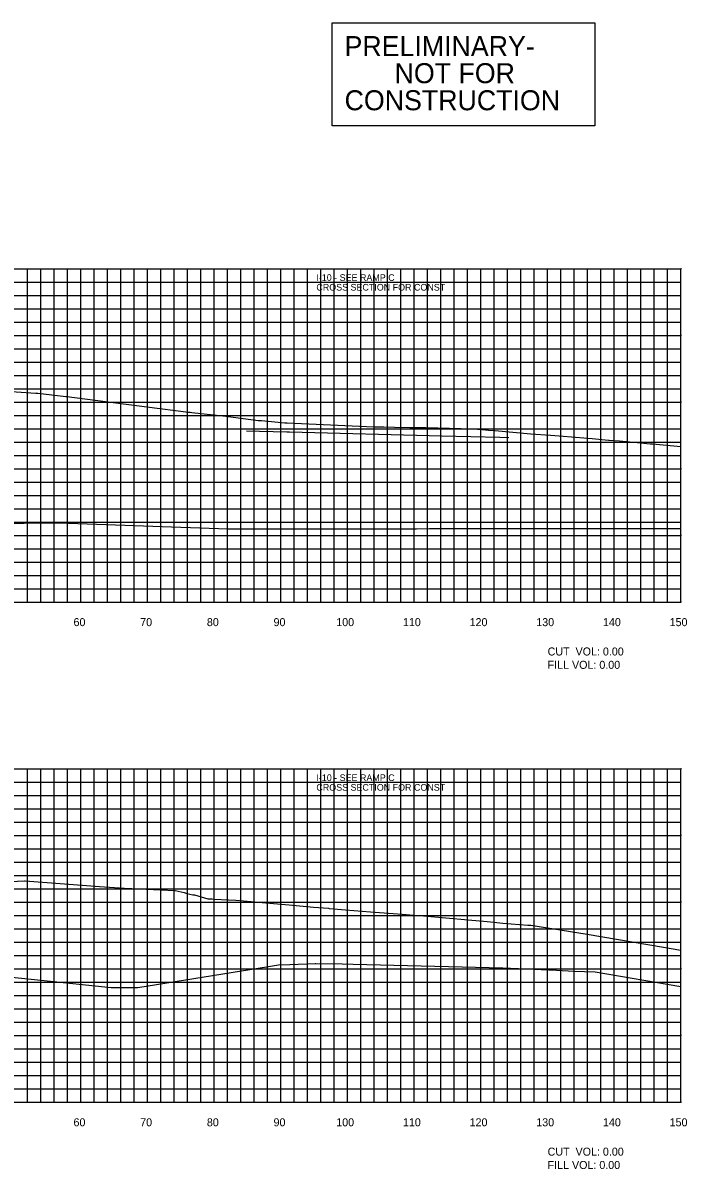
# Model space of a CAD drawing. Extents: x 1800880 to 1814006, y 250083 to 250560.
# Drawn here: x 1809822.3 to 1809921.9, y 250089.4 to 250261.3 of the extents above; entities that cross this region are included whole.
import ezdxf

# ---------------------------------------------------------------- set-up
doc = ezdxf.new("R2010")
doc.units = 0
for name, color, linetype in [('CL-CNST', 7, 'Continuous'), ('DESIGN - DRAINAGE - Bridges', 7, 'Continuous'), ('DRAINAGETXT', 7, 'Continuous'), ('EPTEXT', 7, 'Continuous'), ('Level 32', 7, 'Continuous'), ('Level 46', 7, 'Continuous'), ('Level 62', 7, 'Continuous')]:
    doc.layers.add(name, color=color, linetype=linetype)

msp = doc.modelspace()

# ---------------------------------------------------------------- linework, layer by layer
at = {"layer": 'CL-CNST'}
for points in [[(1809818.3, 250206.17), (1809824.23, 250205.75), (1809824.54, 250205.75), (1809828.73, 250205.28), (1809828.91, 250205.28), (1809840.91, 250203.73), (1809847.13, 250202.9), (1809847.4, 250202.9), (1809847.65, 250202.89), (1809852.73, 250202.3), (1809857.58, 250201.65), (1809857.93, 250201.65), (1809858.08, 250201.65), (1809861.59, 250201.34), (1809861.95, 250201.3), (1809874.92, 250200.73), (1809876.2, 250200.71), (1809876.42, 250200.71), (1809878.06, 250200.68), (1809880.35, 250200.64), (1809882.75, 250200.6), (1809884.52, 250200.56), (1809889.81, 250200.43), (1809891.17, 250200.31), (1809892.11, 250200.23), (1809893.07, 250200.15), (1809898.46, 250199.69), (1809901.44, 250199.46), (1809902.75, 250199.35), (1809905.18, 250199.17), (1809907.67, 250198.95), (1809910.14, 250198.74), (1809910.22, 250198.74), (1809911.77, 250198.61), (1809913.32, 250198.47), (1809914.41, 250198.38), (1809916.4, 250198.19), (1809916.75, 250198.16), (1809921, 250197.76)], [(1809819.38, 250132.51), (1809822.53, 250132.62), (1809822.64, 250132.62), (1809833.8, 250131.77), (1809838.31, 250131.48), (1809838.66, 250131.49), (1809845.09, 250131.21), (1809845.16, 250131.21), (1809846.48, 250130.87), (1809846.91, 250130.76), (1809847.8, 250130.53), (1809848.05, 250130.52), (1809850.04, 250129.95), (1809850.69, 250129.92), (1809850.97, 250129.91), (1809853.14, 250129.79), (1809854.23, 250129.73), (1809856.54, 250129.53), (1809858.75, 250129.34), (1809862.26, 250129.03), (1809865.91, 250128.71), (1809868.12, 250128.52), (1809868.23, 250128.51), (1809868.29, 250128.5), (1809870.71, 250128.31), (1809874.46, 250128.01), (1809877.86, 250127.73), (1809879.19, 250127.64), (1809881.53, 250127.46), (1809881.97, 250127.43), (1809882.39, 250127.4), (1809889.07, 250126.79), (1809891.93, 250126.52), (1809893.38, 250126.39), (1809894.26, 250126.31), (1809898.02, 250126), (1809898.38, 250126), (1809898.49, 250126), (1809906.64, 250124.67), (1809906.91, 250124.66), (1809918.38, 250122.67), (1809921, 250122.25)]]:
    msp.add_lwpolyline(points, dxfattribs=at)
at = {"layer": 'DESIGN - DRAINAGE - Bridges'}
for p, q in [((1809921, 250174.43), (1809921, 250224.43)), ((1809921.06, 250224.43), (1809921, 250224.43)), ((1809921.06, 250214.43), (1809921, 250214.43)), ((1809921.06, 250204.43), (1809921, 250204.43)), ((1809921.06, 250194.43), (1809921, 250194.43)), ((1809921.06, 250184.43), (1809921, 250184.43)), ((1809621, 250174.43), (1809921, 250174.43)), ((1809831, 250174.37), (1809831, 250174.43)), ((1809841, 250174.37), (1809841, 250174.43)), ((1809851, 250174.37), (1809851, 250174.43)), ((1809861, 250174.37), (1809861, 250174.43)), ((1809871, 250174.37), (1809871, 250174.43)), ((1809881, 250174.37), (1809881, 250174.43)), ((1809891, 250174.37), (1809891, 250174.43)), ((1809901, 250174.37), (1809901, 250174.43)), ((1809911, 250174.37), (1809911, 250174.43)), ((1809921, 250174.37), (1809921, 250174.43)), ((1809921.06, 250174.43), (1809921, 250174.43)), ((1809921, 250099.43), (1809921, 250149.43)), ((1809921.06, 250149.43), (1809921, 250149.43)), ((1809921.06, 250139.43), (1809921, 250139.43)), ((1809921.06, 250129.43), (1809921, 250129.43)), ((1809921.06, 250119.43), (1809921, 250119.43)), ((1809921.06, 250109.43), (1809921, 250109.43)), ((1809621, 250099.43), (1809921, 250099.43)), ((1809831, 250099.37), (1809831, 250099.43)), ((1809841, 250099.37), (1809841, 250099.43)), ((1809851, 250099.37), (1809851, 250099.43)), ((1809861, 250099.37), (1809861, 250099.43)), ((1809871, 250099.37), (1809871, 250099.43)), ((1809881, 250099.37), (1809881, 250099.43)), ((1809891, 250099.37), (1809891, 250099.43)), ((1809901, 250099.37), (1809901, 250099.43)), ((1809911, 250099.37), (1809911, 250099.43)), ((1809921, 250099.37), (1809921, 250099.43)), ((1809921.06, 250099.43), (1809921, 250099.43))]:
    msp.add_line(p, q, dxfattribs=at)
at = {"layer": 'Level 32'}
msp.add_lwpolyline([(1809868.68, 250261.29), (1809908.08, 250261.29), (1809908.08, 250245.85), (1809868.68, 250245.85)], close=True, dxfattribs=at)
at = {"layer": 'Level 46'}
for p, q in [((1809621, 250224.43), (1809921, 250224.43)), ((1809823, 250174.43), (1809823, 250224.43)), ((1809825, 250174.43), (1809825, 250224.43)), ((1809827, 250174.43), (1809827, 250224.43)), ((1809829, 250174.43), (1809829, 250224.43)), ((1809831, 250174.43), (1809831, 250224.43)), ((1809833, 250174.43), (1809833, 250224.43)), ((1809835, 250174.43), (1809835, 250224.43)), ((1809837, 250174.43), (1809837, 250224.43)), ((1809839, 250174.43), (1809839, 250224.43)), ((1809841, 250174.43), (1809841, 250224.43)), ((1809843, 250174.43), (1809843, 250224.43)), ((1809845, 250174.43), (1809845, 250224.43)), ((1809847, 250174.43), (1809847, 250224.43)), ((1809849, 250174.43), (1809849, 250224.43)), ((1809851, 250174.43), (1809851, 250224.43)), ((1809853, 250174.43), (1809853, 250224.43)), ((1809855, 250174.43), (1809855, 250224.43)), ((1809857, 250174.43), (1809857, 250224.43)), ((1809859, 250174.43), (1809859, 250224.43)), ((1809861, 250174.43), (1809861, 250224.43)), ((1809863, 250174.43), (1809863, 250224.43)), ((1809865, 250174.43), (1809865, 250224.43)), ((1809867, 250174.43), (1809867, 250224.43)), ((1809869, 250174.43), (1809869, 250224.43)), ((1809871, 250174.43), (1809871, 250224.43)), ((1809873, 250174.43), (1809873, 250224.43)), ((1809875, 250174.43), (1809875, 250224.43)), ((1809877, 250174.43), (1809877, 250224.43)), ((1809879, 250174.43), (1809879, 250224.43)), ((1809881, 250174.43), (1809881, 250224.43)), ((1809883, 250174.43), (1809883, 250224.43)), ((1809885, 250174.43), (1809885, 250224.43)), ((1809887, 250174.43), (1809887, 250224.43)), ((1809889, 250174.43), (1809889, 250224.43)), ((1809891, 250174.43), (1809891, 250224.43)), ((1809893, 250174.43), (1809893, 250224.43)), ((1809895, 250174.43), (1809895, 250224.43)), ((1809897, 250174.43), (1809897, 250224.43)), ((1809899, 250174.43), (1809899, 250224.43)), ((1809901, 250174.43), (1809901, 250224.43)), ((1809903, 250174.43), (1809903, 250224.43)), ((1809905, 250174.43), (1809905, 250224.43)), ((1809907, 250174.43), (1809907, 250224.43)), ((1809909, 250174.43), (1809909, 250224.43)), ((1809911, 250174.43), (1809911, 250224.43)), ((1809913, 250174.43), (1809913, 250224.43)), ((1809915, 250174.43), (1809915, 250224.43)), ((1809917, 250174.43), (1809917, 250224.43)), ((1809919, 250174.43), (1809919, 250224.43)), ((1809921, 250174.43), (1809921, 250224.43)), ((1809621, 250222.43), (1809921, 250222.43)), ((1809621, 250220.43), (1809921, 250220.43)), ((1809621, 250218.43), (1809921, 250218.43)), ((1809621, 250216.43), (1809921, 250216.43)), ((1809621, 250214.43), (1809921, 250214.43)), ((1809621, 250212.43), (1809921, 250212.43)), ((1809621, 250210.43), (1809921, 250210.43)), ((1809621, 250208.43), (1809921, 250208.43)), ((1809621, 250206.43), (1809921, 250206.43)), ((1809621, 250204.43), (1809921, 250204.43)), ((1809621, 250202.43), (1809921, 250202.43)), ((1809621, 250200.43), (1809921, 250200.43)), ((1809621, 250198.43), (1809921, 250198.43)), ((1809621, 250196.43), (1809921, 250196.43)), ((1809621, 250194.43), (1809921, 250194.43)), ((1809621, 250192.43), (1809921, 250192.43)), ((1809621, 250190.43), (1809921, 250190.43)), ((1809621, 250188.43), (1809921, 250188.43)), ((1809621, 250186.43), (1809921, 250186.43)), ((1809621, 250184.43), (1809921, 250184.43)), ((1809621, 250182.43), (1809921, 250182.43)), ((1809621, 250180.43), (1809921, 250180.43)), ((1809621, 250178.43), (1809921, 250178.43)), ((1809621, 250176.43), (1809921, 250176.43)), ((1809621, 250174.43), (1809921, 250174.43)), ((1809621, 250149.43), (1809921, 250149.43)), ((1809823, 250099.43), (1809823, 250149.43)), ((1809825, 250099.43), (1809825, 250149.43)), ((1809827, 250099.43), (1809827, 250149.43)), ((1809829, 250099.43), (1809829, 250149.43)), ((1809831, 250099.43), (1809831, 250149.43)), ((1809833, 250099.43), (1809833, 250149.43)), ((1809835, 250099.43), (1809835, 250149.43)), ((1809837, 250099.43), (1809837, 250149.43)), ((1809839, 250099.43), (1809839, 250149.43)), ((1809841, 250099.43), (1809841, 250149.43)), ((1809843, 250099.43), (1809843, 250149.43)), ((1809845, 250099.43), (1809845, 250149.43)), ((1809847, 250099.43), (1809847, 250149.43)), ((1809849, 250099.43), (1809849, 250149.43)), ((1809851, 250099.43), (1809851, 250149.43)), ((1809853, 250099.43), (1809853, 250149.43)), ((1809855, 250099.43), (1809855, 250149.43)), ((1809857, 250099.43), (1809857, 250149.43)), ((1809859, 250099.43), (1809859, 250149.43)), ((1809861, 250099.43), (1809861, 250149.43)), ((1809863, 250099.43), (1809863, 250149.43)), ((1809865, 250099.43), (1809865, 250149.43)), ((1809867, 250099.43), (1809867, 250149.43)), ((1809869, 250099.43), (1809869, 250149.43)), ((1809871, 250099.43), (1809871, 250149.43)), ((1809873, 250099.43), (1809873, 250149.43)), ((1809875, 250099.43), (1809875, 250149.43)), ((1809877, 250099.43), (1809877, 250149.43)), ((1809879, 250099.43), (1809879, 250149.43)), ((1809881, 250099.43), (1809881, 250149.43)), ((1809883, 250099.43), (1809883, 250149.43)), ((1809885, 250099.43), (1809885, 250149.43)), ((1809887, 250099.43), (1809887, 250149.43)), ((1809889, 250099.43), (1809889, 250149.43)), ((1809891, 250099.43), (1809891, 250149.43)), ((1809893, 250099.43), (1809893, 250149.43)), ((1809895, 250099.43), (1809895, 250149.43)), ((1809897, 250099.43), (1809897, 250149.43)), ((1809899, 250099.43), (1809899, 250149.43)), ((1809901, 250099.43), (1809901, 250149.43)), ((1809903, 250099.43), (1809903, 250149.43)), ((1809905, 250099.43), (1809905, 250149.43)), ((1809907, 250099.43), (1809907, 250149.43)), ((1809909, 250099.43), (1809909, 250149.43)), ((1809911, 250099.43), (1809911, 250149.43)), ((1809913, 250099.43), (1809913, 250149.43)), ((1809915, 250099.43), (1809915, 250149.43)), ((1809917, 250099.43), (1809917, 250149.43)), ((1809919, 250099.43), (1809919, 250149.43)), ((1809921, 250099.43), (1809921, 250149.43)), ((1809621, 250147.43), (1809921, 250147.43)), ((1809621, 250145.43), (1809921, 250145.43)), ((1809621, 250143.43), (1809921, 250143.43)), ((1809621, 250141.43), (1809921, 250141.43)), ((1809621, 250139.43), (1809921, 250139.43)), ((1809621, 250137.43), (1809921, 250137.43)), ((1809621, 250135.43), (1809921, 250135.43)), ((1809621, 250133.43), (1809921, 250133.43)), ((1809621, 250131.43), (1809921, 250131.43)), ((1809621, 250129.43), (1809921, 250129.43)), ((1809621, 250127.43), (1809921, 250127.43)), ((1809621, 250125.43), (1809921, 250125.43)), ((1809621, 250123.43), (1809921, 250123.43)), ((1809621, 250121.43), (1809921, 250121.43)), ((1809621, 250119.43), (1809921, 250119.43)), ((1809621, 250117.43), (1809921, 250117.43)), ((1809621, 250115.43), (1809921, 250115.43)), ((1809621, 250113.43), (1809921, 250113.43)), ((1809621, 250111.43), (1809921, 250111.43)), ((1809621, 250109.43), (1809921, 250109.43)), ((1809621, 250107.43), (1809921, 250107.43)), ((1809621, 250105.43), (1809921, 250105.43)), ((1809621, 250103.43), (1809921, 250103.43)), ((1809621, 250101.43), (1809921, 250101.43)), ((1809621, 250099.43), (1809921, 250099.43))]:
    msp.add_line(p, q, dxfattribs=at)
at = {"layer": 'Level 62'}
for points in [[(1809855.86, 250200.14), (1809857.77, 250200.09), (1809861.87, 250199.98), (1809862.28, 250199.97), (1809885.12, 250199.37), (1809893.81, 250199.15), (1809895.16, 250199.11)], [(1809621, 250186.58), (1809633.48, 250186.5), (1809635.86, 250186.5), (1809661.24, 250186.43), (1809666.01, 250186.45), (1809688.99, 250186.47), (1809695.84, 250186.51), (1809716.75, 250186.15), (1809725.4, 250186.2), (1809744.5, 250186.4), (1809762.12, 250186.29), (1809772.26, 250186.35), (1809789.71, 250186.64), (1809800.01, 250186.71), (1809817.25, 250186.24), (1809827.77, 250186.3), (1809853.03, 250185.43), (1809855.53, 250185.44), (1809881.36, 250185.44), (1809883.28, 250185.45), (1809909.23, 250185.45), (1809911.04, 250185.46), (1809921, 250185.46)], [(1809755.37, 250124.99), (1809757.56, 250124.76), (1809763.06, 250124.19), (1809781.58, 250122.26), (1809825, 250117.75), (1809835.53, 250116.65), (1809837.19, 250116.64), (1809839.55, 250116.63), (1809859.12, 250119.79), (1809860.64, 250120.04), (1809862.34, 250120.1), (1809866.16, 250120.23), (1809866.24, 250120.24), (1809870.18, 250120.21), (1809871.82, 250120.16), (1809894.28, 250119.58), (1809896.63, 250119.48), (1809902.31, 250119.23), (1809904.94, 250119.11), (1809908.14, 250118.97), (1809921, 250116.79)]]:
    msp.add_lwpolyline(points, dxfattribs=at)

# ---------------------------------------------------------------- texts
for s, p in [('60', (1809829.9, 250170.83)), ('70', (1809839.9, 250170.83)), ('80', (1809849.9, 250170.83)), ('90', (1809859.9, 250170.83)), ('100', (1809869.3, 250170.83)), ('110', (1809879.3, 250170.83)), ('120', (1809889.3, 250170.83)), ('130', (1809899.3, 250170.83)), ('140', (1809909.3, 250170.83)), ('150', (1809919.3, 250170.83)), ('60', (1809829.9, 250095.83)), ('70', (1809839.9, 250095.83)), ('80', (1809849.9, 250095.83)), ('90', (1809859.9, 250095.83)), ('100', (1809869.3, 250095.83)), ('110', (1809879.3, 250095.83)), ('120', (1809889.3, 250095.83)), ('130', (1809899.3, 250095.83)), ('140', (1809909.3, 250095.83)), ('150', (1809919.3, 250095.83))]:
    msp.add_text(s, height=1.2).set_placement(p)
at = {"layer": 'DRAINAGETXT'}
for s, p in [('CUT  VOL: 0.00', (1809901, 250166.43)), ('FILL VOL: 0.00', (1809901, 250164.43)), ('CUT  VOL: 0.00', (1809901, 250091.43)), ('FILL VOL: 0.00', (1809901, 250089.43))]:
    msp.add_text(s, height=1.2, dxfattribs=at).set_placement(p)
at = {"layer": 'EPTEXT'}
for s, p in [('CROSS SECTION FOR CONST ', (1809866.32, 250221.15)), ('I-10 - SEE RAMP C', (1809866.32, 250222.6)), ('I-10 - SEE RAMP C', (1809866.32, 250147.6)), ('CROSS SECTION FOR CONST ', (1809866.32, 250146.15))]:
    msp.add_text(s, height=1, dxfattribs=at).set_placement(p)
at = {"layer": 'Level 32'}
for s, p in [('PRELIMINARY-', (1809870.54, 250256.31)), ('NOT FOR', (1809878.05, 250252.25)), ('CONSTRUCTION', (1809870.55, 250248.19))]:
    msp.add_text(s, height=3, dxfattribs=at).set_placement(p)

doc.saveas('drawing.dxf')
